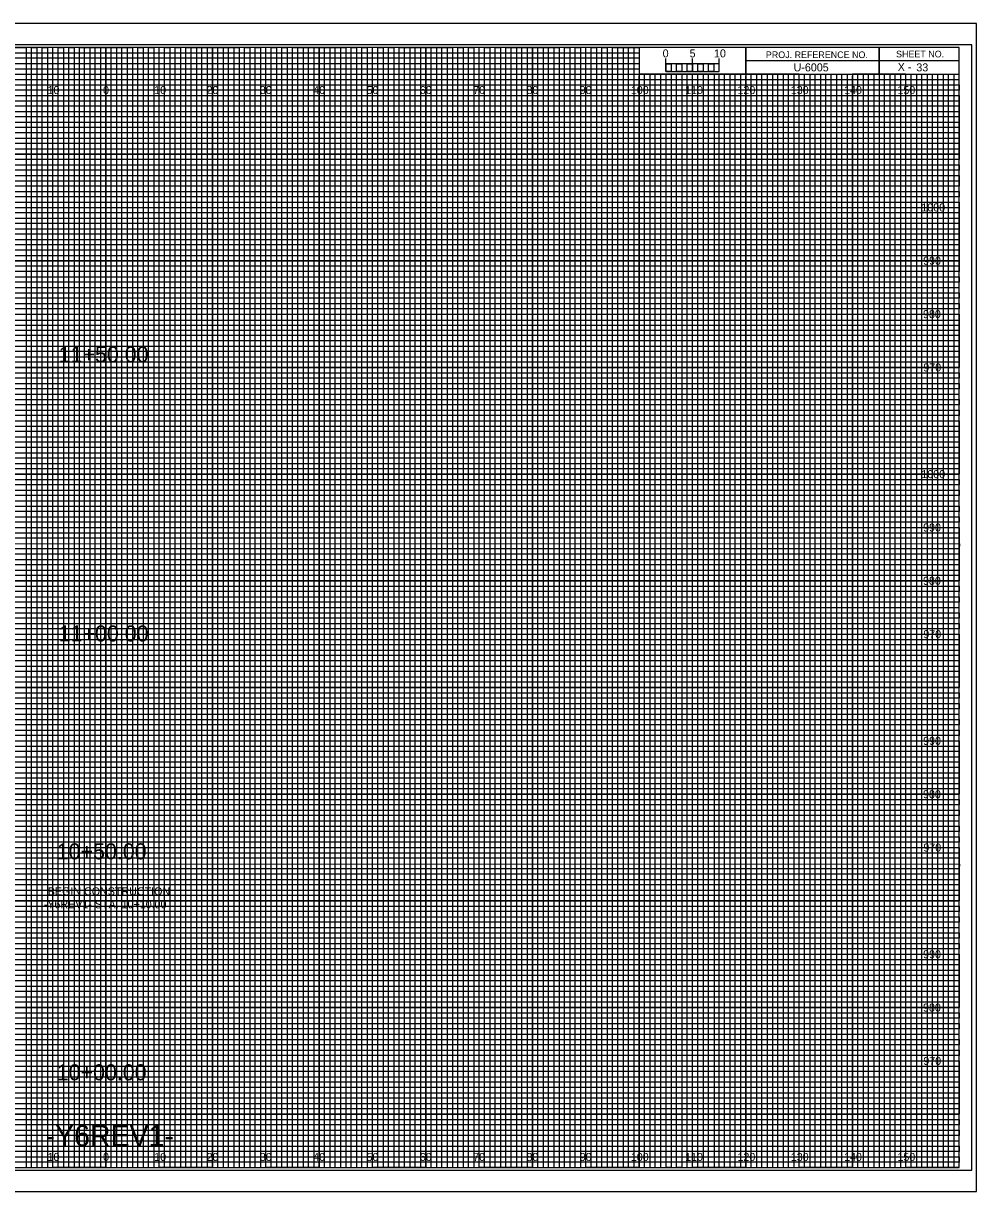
# Model space of a CAD drawing. Extents: x -13 to 323, y -5 to 215.
# Drawn here: x 144.5 to 323.3, y -4.5 to 214.5 of the extents above; entities that cross this region are included whole.
import ezdxf

# ---------------------------------------------------------------- set-up
doc = ezdxf.new("R2010")
doc.units = 0
for name, color, linetype in [('Prop XS Alignment Label', 7, 'Continuous'), ('Prop XS Bar Scale Labels', 7, 'Continuous'), ('Prop XS Elevation Labels', 7, 'Continuous'), ('Prop XS Label Text', 7, 'Continuous'), ('Prop XS Offset Labels', 7, 'Continuous'), ('Prop XS Project Number', 7, 'Continuous'), ('Prop XS Sheet Number', 7, 'Continuous'), ('Prop XS Station Labels', 7, 'Continuous'), ('Sheet Cross Section CELL', 7, 'Continuous'), ('Sheet Cross Section Grid Major CELL', 7, 'Continuous'), ('Sheet Cross Section Grid Middle CELL', 7, 'Continuous'), ('Sheet Cross Section Grid Minor 1 CELL', 7, 'Continuous'), ('Sheet Cross Section Grid Minor 2 CELL', 7, 'Continuous'), ('Sheet Cross Section Scale CELL', 7, 'Continuous'), ('Sheet Cutting Line CELL', 7, 'Continuous'), ('Sheet DOT Grid CELL', 7, 'Continuous'), ('Sheet Plot Border Inside CELL', 7, 'Continuous'), ('Sheet Plot Border Outside CELL', 7, 'Continuous')]:
    doc.layers.add(name, color=color, linetype=linetype)

msp = doc.modelspace()

# ---------------------------------------------------------------- linework, layer by layer
at = {"layer": 'Sheet Cross Section CELL'}
for p, q in [((305, 210), (305, 205)), ((305, 205), (305, 210)), ((280, 207.5), (280, 205)), ((320, 207.49), (280, 207.49)), ((280, 205), (320, 205))]:
    msp.add_line(p, q, dxfattribs=at)
for points in [[(320, 210), (0, 210), (0, 0), (320, 0)], [(280, 210), (260, 210), (260, 205.03), (280, 205.03)], [(320, 210), (280, 210), (280, 205), (320, 205)]]:
    msp.add_lwpolyline(points, close=True, dxfattribs=at)
at = {"layer": 'Sheet Cross Section Grid Major CELL'}
for p, q in [((150, 210), (140, 210)), ((150, 0), (150, 210)), ((170, 210), (160, 210)), ((160, 210), (160, 0)), ((170, 0), (170, 210)), ((190, 210), (180, 210)), ((180, 210), (180, 0)), ((190, 0), (190, 210)), ((210, 210), (200, 210)), ((200, 210), (200, 0)), ((210, 0), (210, 210)), ((230, 210), (220, 210)), ((220, 210), (220, 0)), ((230, 0), (230, 210)), ((250, 210), (240, 210)), ((240, 210), (240, 0)), ((250, 0), (250, 210)), ((260, 210), (260, 0)), ((270, 0), (270, 205)), ((290, 205), (280, 205)), ((280, 205), (280, 0)), ((290, 0), (290, 205)), ((310, 205), (300, 205)), ((300, 205), (300, 0)), ((310, 0), (310, 205)), ((160, 0), (150, 0)), ((180, 0), (170, 0)), ((200, 0), (190, 0)), ((220, 0), (210, 0)), ((240, 0), (230, 0)), ((260, 0), (250, 0)), ((280, 0), (270, 0)), ((300, 0), (290, 0)), ((320, 0), (310, 0)), ((320, 0), (320, 0))]:
    msp.add_line(p, q, dxfattribs=at)
for points in [[(0, 200), (320, 200), (320, 190), (0, 190)], [(0, 180), (320, 180), (320, 170), (0, 170)], [(0, 160), (320, 160), (320, 150), (0, 150)], [(0, 140), (320, 140), (320, 130), (0, 130)], [(0, 120), (320, 120), (320, 110), (0, 110)], [(0, 100), (320, 100), (320, 90), (0, 90)], [(0, 80), (320, 80), (320, 70), (0, 70)], [(0, 60), (320, 60), (320, 50), (0, 50)], [(0, 40), (320, 40), (320, 30), (0, 30)], [(0, 20), (320, 20), (320, 10), (0, 10)]]:
    msp.add_lwpolyline(points, dxfattribs=at)
at = {"layer": 'Sheet Cross Section Grid Middle CELL'}
for points in [[(135, 210), (145, 210), (145, 0), (155, 0), (155, 210), (165, 210), (165, 0), (175, 0), (175, 210), (185, 210), (185, 0), (195, 0), (195, 210), (205, 210), (205, 0), (215, 0), (215, 210), (225, 210), (225, 0), (235, 0), (235, 210), (245, 210), (245, 0), (255, 0), (255, 210), (259.93, 210), (260, 210), (260, 205), (264.99, 205), (264.99, 0), (275, 0), (275, 205), (285, 205), (285, 0), (295, 0), (295, 205), (305, 205), (305, 0), (315, 0), (315, 205)], [(0, 205), (275, 205)], [(0, 185), (320, 185), (320, 195), (0, 195)], [(0, 165), (320, 165), (320, 175), (0, 175)], [(0, 145), (320, 145), (320, 155), (0, 155)], [(0, 125), (320, 125), (320, 135), (0, 135)], [(0, 105), (320, 105), (320, 115), (0, 115)], [(0, 85), (320, 85), (320, 95), (0, 95)], [(0, 65), (320, 65), (320, 75), (0, 75)], [(0, 45), (320, 45), (320, 55), (0, 55)], [(0, 25), (320, 25), (320, 35), (0, 35)], [(0, 5), (320, 5), (320, 15), (0, 15)]]:
    msp.add_lwpolyline(points, dxfattribs=at)
at = {"layer": 'Sheet Cross Section Grid Minor 1 CELL'}
for p, q in [((0, 209), (260, 209)), ((260, 209), (260, 207.98)), ((260, 207.98), (0, 207.98)), ((0, 207), (260, 207)), ((260, 205.89), (0, 205.89)), ((260, 207), (260, 205.89)), ((0, 204), (320, 204))]:
    msp.add_line(p, q, dxfattribs=at)
for points in [[(0, 203), (270, 203), (320, 203), (320, 202), (0, 202)], [(0, 201), (320, 201), (320, 199), (0, 199)], [(0, 198), (320, 198), (320, 197), (0, 196.98)], [(0, 196), (320, 196), (320, 194), (0, 194)], [(0, 193), (320, 193), (320, 192), (0, 192)], [(0, 191), (320, 191), (320, 189), (0, 189)], [(0, 188), (320, 188), (320, 187), (0, 187)], [(0, 186), (320, 186), (320, 184), (0, 184)], [(0, 183), (320, 183), (320, 182), (0, 182)], [(0, 181), (320, 181), (320, 179), (0, 179)], [(0, 178), (320, 178), (320, 177), (0, 177)], [(0, 176), (320, 176), (320, 173.95), (320, 173), (320, 172), (0, 172)], [(0, 174), (320, 174), (320, 173), (0, 173)], [(0, 171), (320, 171), (320, 169), (0, 169.03)], [(0, 169.03), (320, 169), (320, 168), (0, 168)], [(0, 167), (320, 167), (320, 166), (0, 166)], [(0, 164), (320, 164), (320, 163), (0, 163)], [(0, 162), (320, 162), (320, 161), (0, 161)], [(-0.07, 158.89), (320, 158.89), (320, 157.88), (-0.07, 157.88)], [(0, 157), (320, 157), (320, 156), (0, 156)], [(0, 154), (320, 154), (320, 153), (0, 153)], [(0, 152), (320, 152), (320, 151), (0, 151)], [(0, 149), (320, 149), (320, 148), (0, 148)], [(0, 147), (320, 147), (320, 146), (0, 146)], [(0, 144), (320, 144), (320, 143), (0, 143)], [(0, 142), (320, 142), (320, 141), (0, 141)], [(0, 139), (320, 139), (319.99, 137.98), (0, 138)], [(0, 137), (320, 137), (320, 136), (0, 136)], [(0, 134), (320, 134), (320, 133), (0, 133)], [(0, 132), (320, 132), (320, 131), (0, 131)], [(0, 129), (320, 129), (320, 128), (0, 128)], [(0, 127), (320, 127), (320, 126), (0, 126)], [(0, 124), (320, 124), (320, 123), (0, 123)], [(0, 122), (320, 122), (320, 121), (0, 121)], [(0, 119), (320, 119), (320, 118), (0, 118)], [(0, 116.99), (320.07, 116.91), (320, 116), (0, 116)], [(0, 114), (320, 114), (320, 113), (0, 113)], [(0, 112), (320, 112), (320, 111), (0, 111)], [(0, 109), (320, 109), (320, 108), (0, 108)], [(0, 107), (320, 107), (320, 106), (0, 106)], [(0, 104), (320, 104), (320, 103), (0, 103)], [(0, 102), (320, 102), (320, 101), (0, 101)], [(0, 99), (320, 99), (320, 98), (0, 98)], [(0, 97), (320, 97), (320, 96), (0, 96)], [(0, 94), (320, 94), (320, 93), (0, 93)], [(0, 92), (320, 92), (320, 91), (0, 91)], [(0, 89), (320, 89), (320, 88), (0, 88)], [(0, 87), (320, 87), (320, 86), (0, 86)], [(0, 84), (320, 84), (320, 83), (0, 83)], [(0, 82), (320, 82), (320, 81), (0, 81)], [(0, 79), (320, 79), (319.99, 77.98), (0, 78)], [(0, 77), (320, 77), (320, 76), (0, 76)], [(0, 74), (320, 74), (320, 73), (0, 73)], [(0, 72), (320, 72), (320, 71), (0, 71)], [(0, 69), (320, 69), (320, 68), (0, 68)], [(0, 67), (320, 67), (320, 66), (0, 66)], [(0, 64), (320, 64), (320, 63), (0, 63)], [(0, 62), (320, 62), (320, 61), (0, 61)], [(0, 59), (320, 59), (320, 58), (0, 58)], [(0, 56.99), (320.07, 56.91), (320, 56), (0, 56)], [(0, 54), (320, 54), (320, 53), (0, 53)], [(0, 52), (320, 52), (320, 51), (0, 51)], [(0, 49), (320, 49), (320, 48), (0, 48)], [(0, 47), (320, 47), (320, 46), (0, 46)], [(0, 44), (320, 44), (320, 43), (0, 43)], [(0, 42), (320, 42), (320, 41), (0, 41)], [(0, 39), (320, 39), (320, 38), (0, 38)], [(0, 37), (320, 37), (320, 36), (0, 36)], [(0, 34), (320, 34), (320, 33), (0, 33)], [(0, 32), (320, 32), (320, 31), (0, 31)], [(0, 29), (320, 29), (320, 28), (0, 28)], [(0, 27), (320, 27), (320, 26), (0, 26)], [(0, 24), (320, 24), (320, 23), (0, 23)], [(0, 22), (320, 22), (320, 21), (0, 21)], [(0, 19), (320, 19), (320, 18), (0, 18)], [(0, 17), (320, 17), (320, 16), (0, 16)], [(0, 14), (320, 14), (320, 13), (0, 13)], [(0, 12), (320, 12), (320, 11), (0, 11)], [(0, 9), (320, 9), (320, 8), (0, 8)], [(0, 7), (320, 7), (320, 6), (0, 6)], [(0, 4), (320, 4), (320, 3), (0, 3)], [(0, 2), (320, 2), (320, 1), (0, 1)]]:
    msp.add_lwpolyline(points, dxfattribs=at)
at = {"layer": 'Sheet Cross Section Grid Minor 2 CELL'}
for p, q in [((267, 205), (266.01, 205)), ((266.01, 205), (266.01, 0)), ((267, 0), (267, 205)), ((269, 205), (268, 205)), ((268, 205), (268, 0)), ((269, 0), (269, 205)), ((266.01, 0), (265, 0)), ((268, 0), (267, 0))]:
    msp.add_line(p, q, dxfattribs=at)
for points in [[(145, 0), (146, 0), (146, 210), (147, 210), (147, 0)], [(147, 0), (148, 0), (148, 210), (149, 210), (149, 0)], [(150, 0), (151, 0), (151, 210), (152, 210), (152, 0)], [(152, 0), (153, 0), (153, 210), (154, 210), (154, 0)], [(155, 0), (156, 0), (156, 210), (157, 210), (157, 0)], [(157, 0), (158, 0), (158, 210), (159, 210), (159, 0)], [(160, 0), (161, 0), (161, 210), (162, 210), (162, 0)], [(162, 0), (163, 0), (163, 210), (164, 210), (164, 0)], [(165, 0), (166, 0), (166, 210), (167, 210), (167, 0)], [(167, 0), (168, 0), (168, 210), (169, 210), (169, 0)], [(170, 0), (171, 0), (171, 210), (172, 210), (172, 0)], [(172, 0), (173, 0), (173, 210), (174, 210), (174, 0)], [(175, 0), (176, 0), (176, 210), (177, 210), (177, 0)], [(177, 0), (178, 0), (178, 210), (179, 210), (179, 0)], [(180, 0), (181, 0), (181, 210), (182, 210), (182, 0)], [(182, 0), (183, 0), (183, 210), (184, 210), (184, 0)], [(185, 0), (186, 0), (186, 210), (187, 210), (187, 0)], [(187, 0), (188, 0), (188, 210), (189, 210), (189, 0)], [(190, 0), (191, 0), (191, 210), (192, 210), (192, 0)], [(192, 0), (193, 0), (193, 210), (194, 210), (194, 0)], [(195, 0), (196, 0), (196, 210), (197, 210), (197, 0)], [(197, 0), (198, 0), (198, 210), (199, 210), (199, 0)], [(200, 0), (201, 0), (201, 210), (202, 210), (202, 0)], [(202, 0), (203, 0), (203, 210), (204, 210), (204, 0)], [(205, 0), (206, 0), (206, 210), (207, 210), (207, 0)], [(207, 0), (208, 0), (208, 210), (209, 210), (209, 0)], [(210, 0), (211, 0), (211, 210), (212, 210), (212, 0)], [(212, 0), (213, 0), (213, 210), (214, 210), (214, 0)], [(215, 0), (216, 0), (216, 210), (217, 210), (217, 0)], [(217, 0), (218, 0), (218, 210), (219, 210), (219, 0)], [(220, 0), (221, 0), (221, 210), (222, 210), (222, 0)], [(222, 0), (223, 0), (223, 210), (224, 210), (224, 0)], [(225, 0), (226, 0), (226, 210), (227, 210), (227, 0)], [(227, 0), (228, 0), (228, 210), (229, 210), (229, 0)], [(230, 0), (231, 0), (231, 210), (232, 210), (232, 0)], [(232, 0), (233, 0), (233, 210), (234, 210), (234, 0)], [(235, 0), (236, 0), (236, 210), (237, 210), (237, 0)], [(237, 0), (238, 0), (238, 210), (239, 210), (239, 0)], [(240, 0), (241, 0), (241, 210), (242, 210), (242, 0)], [(242, 0), (243, 0), (243, 210), (244, 210), (244, 0)], [(245, 0), (246, 0), (246, 210), (247, 210), (247, 0)], [(247, 0), (248, 0), (248, 210), (249, 210), (249, 0)], [(250, 0), (251, 0), (251, 210), (252, 210), (252, 0)], [(252, 0), (253, 0), (253, 210), (254, 210), (254, 0)], [(255, 0), (256, 0), (256, 210), (257, 210), (257, 0)], [(257, 0), (258, 0), (258, 210), (259, 210), (259, 0)], [(260, 0), (261, 0), (261, 205), (262.02, 205), (262.02, 0)], [(262, 0), (263, 0), (263, 205), (263.99, 205), (263.99, 0)], [(270, 0), (270.98, 0), (270.98, 205), (272, 205), (272, 0)], [(272, 0), (273, 0), (273, 205), (274.05, 205), (274.05, 0)], [(275, 0), (276, 0), (276, 205), (277, 205), (277, 0)], [(277, 0), (278, 0), (278, 205), (279, 205), (279, 0)], [(280, 0), (281, 0), (281, 205), (282, 205), (282, 0)], [(282, 0), (283, 0), (283, 205), (284, 205), (284, 0)], [(285, 0), (286, 0), (286, 205), (287, 205), (287, 0)], [(287, 0), (288, 0), (288, 205), (289, 205), (289, 0)], [(290, 0), (291, 0), (291, 205), (292, 205), (292, 0)], [(292, 0), (293, 0), (293, 205), (294, 205), (294, 0)], [(295, 0), (296, 0), (296, 205), (297, 205), (297, 0)], [(297, 0), (298, 0), (298, 205), (299, 205), (299, 0)], [(300, 0), (301, 0), (301, 205), (302, 205), (302, 0)], [(302, 0), (303, 0), (303, 205), (304, 205), (304, 0)], [(305, 0), (306, 0), (306, 205), (307, 205), (307, 0)], [(307, 0), (308, 0), (308, 205), (309, 205), (309, 0)], [(310, 0), (311, 0), (311, 205), (312, 205), (312, 0)], [(312, 0), (313, 0), (313, 205), (314, 205), (314, 0)], [(315, 0), (316, 0), (316, 205), (317, 205), (317, 0)], [(317, 0), (318, 0), (318, 205), (319, 205), (319, 0)]]:
    msp.add_lwpolyline(points, dxfattribs=at)
at = {"layer": 'Sheet Cross Section Scale CELL'}
for p, q in [((265, 205.49), (265, 207.9)), ((265, 206.9), (265, 207.9)), ((270, 205.49), (270, 207.9)), ((275, 205.49), (275, 207.9)), ((275, 206.9), (275, 207.9))]:
    msp.add_line(p, q, dxfattribs=at)
for points in [[(275, 206.9), (265, 206.9), (265, 205.49), (275, 205.49)], [(265, 206.9), (266, 206.9), (266, 205.49), (265, 205.49)], [(267, 206.9), (268, 206.9), (268, 205.49), (267, 205.49)], [(269, 206.9), (270, 206.9), (270, 205.49), (269, 205.49)], [(271, 206.9), (272, 206.9), (272, 205.49), (271, 205.49)], [(273, 206.9), (274, 206.9), (274, 205.49), (273, 205.49)]]:
    msp.add_lwpolyline(points, close=True, dxfattribs=at)
at = {"layer": 'Sheet Cutting Line CELL'}
for p, q in [((323.3, 214.5), (-13.4, 214.5)), ((-13.4, -4.5), (323.3, -4.5))]:
    msp.add_line(p, q, dxfattribs=at)
at = {"layer": 'Sheet DOT Grid CELL'}
for p, q in [((150, 0), (150, 210)), ((160, 0), (160, 210)), ((170, 0), (170, 210)), ((180, 0), (180, 210)), ((190, 0), (190, 210)), ((200, 0), (200, 210)), ((210, 0), (210, 210)), ((220, 0), (220, 210)), ((230, 0), (230, 210)), ((240, 0), (240, 210)), ((250, 0), (250, 210)), ((260, 0), (260, 204.69)), ((270, 0), (270, 204.69)), ((280, 0), (280, 204.69)), ((290, 0), (290, 204.69)), ((300, 0), (300, 204.69)), ((310, 0), (310, 204.69)), ((0, 200), (320, 200)), ((0, 190), (320, 190)), ((0, 180), (320, 180)), ((0, 170), (320, 170)), ((0, 160), (320, 160)), ((0, 150), (320, 150)), ((0, 140), (320, 140)), ((0, 130), (320, 130)), ((0, 120), (320, 120)), ((0, 110), (320, 110)), ((0, 100), (320, 100)), ((0, 90), (320, 90)), ((0, 80), (320, 80)), ((0, 70), (320, 70)), ((0, 60), (320, 60)), ((0, 50), (320, 50)), ((0, 40), (320, 40)), ((0, 30), (320, 30)), ((0, 20), (320, 20)), ((0, 10), (320, 10))]:
    msp.add_line(p, q, dxfattribs=at)
at = {"layer": 'Sheet Plot Border Inside CELL'}
msp.add_lwpolyline([(-10.8, -0.5), (322.4, -0.5), (322.4, 210.5), (-10.8, 210.5)], close=True, dxfattribs=at)
at = {"layer": 'Sheet Plot Border Outside CELL'}
msp.add_lwpolyline([(-13.4, -4.5), (323.3, -4.5), (323.3, 214.5), (-13.4, 214.5)], close=True, dxfattribs=at)

# ---------------------------------------------------------------- texts
at = {"layer": 'Prop XS Alignment Label'}
msp.add_text('-Y6REV1-', height=4, dxfattribs=at).set_placement((148.67, 4))
at = {"layer": 'Prop XS Bar Scale Labels'}
for s, p in [('5', (269.47, 208.12)), ('10', (274.04, 208.12))]:
    msp.add_text(s, height=1.5, dxfattribs=at).set_placement(p)
at = {"layer": 'Prop XS Elevation Labels'}
for s, p in [('1000', (312.92, 179.25)), ('990', (313.26, 169.25)), ('980', (313.24, 159.25)), ('970', (313.3, 149.25)), ('1000', (312.92, 129.25)), ('990', (313.26, 119.25)), ('980', (313.24, 109.25)), ('970', (313.3, 99.25)), ('990', (313.26, 79.25)), ('980', (313.24, 69.25)), ('970', (313.3, 59.25)), ('990', (313.26, 39.25)), ('980', (313.24, 29.25)), ('970', (313.3, 19.25))]:
    msp.add_text(s, height=1.5, dxfattribs=at).set_placement(p)
at = {"layer": 'Prop XS Label Text'}
for s, p in [('BEGIN CONSTRUCTION', (149.08, 51.05)), ('-Y6REV1- STA. 10+10.00', (148.33, 48.61))]:
    msp.add_text(s, height=1.5, dxfattribs=at).set_placement(p)
at = {"layer": 'Prop XS Offset Labels'}
for s, p in [('10', (149.04, 201.25)), ('0', (159.45, 201.25)), ('0', (159.45, 201.25)), ('10', (169.04, 201.25)), ('20', (178.86, 201.25)), ('30', (188.86, 201.25)), ('40', (198.86, 201.25)), ('50', (208.86, 201.25)), ('60', (218.86, 201.25)), ('70', (228.86, 201.25)), ('80', (238.86, 201.25)), ('90', (248.86, 201.25)), ('100', (258.44, 201.25)), ('110', (268.62, 201.25)), ('120', (278.44, 201.25)), ('130', (288.44, 201.25)), ('140', (298.44, 201.25)), ('150', (308.44, 201.25)), ('10', (149.04, 1.25)), ('0', (159.45, 1.25)), ('0', (159.45, 1.25)), ('10', (169.04, 1.25)), ('20', (178.86, 1.25)), ('30', (188.86, 1.25)), ('40', (198.86, 1.25)), ('50', (208.86, 1.25)), ('60', (218.86, 1.25)), ('70', (228.86, 1.25)), ('80', (238.86, 1.25)), ('90', (248.86, 1.25)), ('100', (258.44, 1.25)), ('110', (268.62, 1.25)), ('120', (278.44, 1.25)), ('130', (288.44, 1.25)), ('140', (298.44, 1.25)), ('150', (308.44, 1.25))]:
    msp.add_text(s, height=1.5, dxfattribs=at).set_placement(p)
at = {"layer": 'Prop XS Project Number'}
msp.add_text('U-6005', height=1.5, dxfattribs=at).set_placement((288.97, 205.5))
at = {"layer": 'Prop XS Sheet Number'}
msp.add_text('33', height=1.5, dxfattribs=at).set_placement((311.99, 205.5))
at = {"layer": 'Prop XS Station Labels'}
for s, p in [('11+50.00', (151.13, 150.95)), ('11+00.00', (151.13, 98.63)), ('10+50.00', (150.77, 57.79)), ('10+00.00', (150.77, 16.37))]:
    msp.add_text(s, height=3, dxfattribs=at).set_placement(p)
at = {"layer": 'Sheet Cross Section CELL'}
for s, height, p in [('PROJ. REFERENCE NO.', 1.25, (283.77, 207.99)), ('SHEET NO.', 1.25, (308.19, 208.12)), ('X -    ', 1.5, (308.5, 205.58))]:
    msp.add_text(s, height=height, dxfattribs=at).set_placement(p)
at = {"layer": 'Sheet Cross Section Scale CELL'}
msp.add_text('0', height=1.5, dxfattribs=at).set_placement((264.41, 208.12))

doc.saveas('drawing.dxf')
